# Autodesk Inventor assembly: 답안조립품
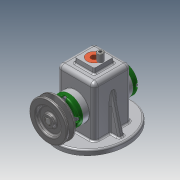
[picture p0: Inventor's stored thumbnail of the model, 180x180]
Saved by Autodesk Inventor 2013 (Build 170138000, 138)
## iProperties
Created: 2017-07
Part Number: 답안조립품
Document SubType Name: Assembly
Designer: Administrator
Author: Administrator
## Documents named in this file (15)
- C:\Users\Administrator\Desktop\470708V1023\답안조립품.iam
- C:\Users\Administrator\Desktop\470708V1023\본체.ipt
- C:\Users\Administrator\Desktop\470708V1023\편심축.ipt
- C:\Users\Administrator\Desktop\470708V1023\베어링 12 x 32 x 10.ipt
- C:\Users\Administrator\Desktop\470708V1023\링크.ipt
- C:\Users\Administrator\Desktop\470708V1023\부시.ipt
- C:\Users\Administrator\Desktop\470708V1023\뒤커버.ipt
- C:\Users\Administrator\Desktop\470708V1023\앞커버.ipt
- C:\Users\Administrator\Desktop\470708V1023\슬라이드.ipt
- C:\Users\Administrator\Desktop\470708V1023\고정핀 1.2 x  8.ipt
- C:\Users\Administrator\Desktop\470708V1023\핀 5 x 18.ipt
- C:\Users\Administrator\Desktop\470708V1023\오일실 12 25 7.ipt
- C:\Users\Administrator\Desktop\470708V1023\볼트 M4 x 12.ipt
- C:\Users\Administrator\Desktop\470708V1023\V벨트풀리.ipt
- C:\Users\Administrator\Desktop\470708V1023\키 4 x 4 x 10.ipt
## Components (3 placed, 3 different names)
1. 고정핀 1.2 x  8:1
2. 핀 5 x 18:1
3. V벨트풀리:1
